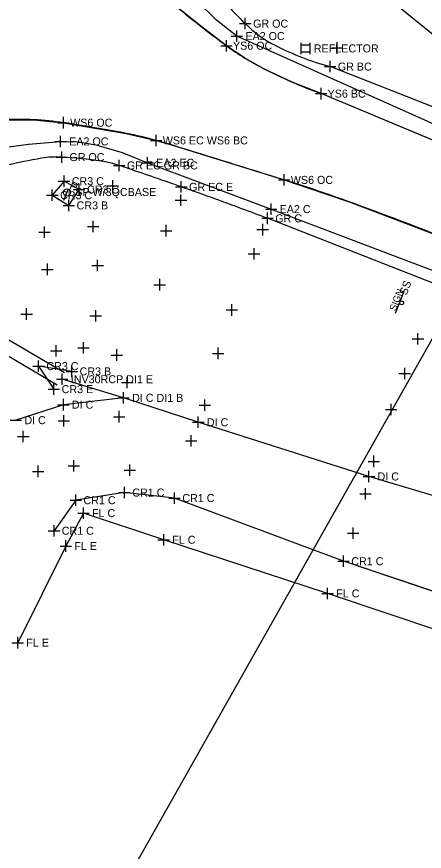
# Model space of a CAD drawing. Extents: x 1324236 to 1326110, y 459090 to 460782.
# Drawn here: x 1325026.2 to 1325097.4, y 459726.6 to 459872.5 of the extents above; entities that cross this region are included whole.
import ezdxf

# ---------------------------------------------------------------- set-up
doc = ezdxf.new("R2010")
doc.units = 0
for name, color, linetype in [('BD_X_Canopy', 7, 'Continuous'), ('DR_X_Ditch', 7, 'Continuous'), ('DR_X_Drive_Pipe', 7, 'Continuous'), ('DR_X_Paved_Gutter', 7, 'Continuous'), ('DT_X_Contour_Minor', 7, 'Continuous'), ('DT_X_Island', 7, 'Continuous'), ('DT_X_Terrain_Ground_Line', 7, 'Continuous'), ('DT_X_Void', 7, 'Continuous'), ('DV_X_Property_Line', 7, 'Continuous'), ('E-RW-ODOT', 7, 'Continuous'), ('PM_X_CL_Double_Solid', 7, 'Continuous'), ('PM_X_Edge_Line', 7, 'Continuous'), ('PM_X_Misc', 7, 'Continuous'), ('PM_X_Parking_Lot_Stall', 7, 'Continuous'), ('PV_X_Shoulder', 7, 'Continuous'), ('RD_X_Concrete_Barrier', 7, 'Continuous'), ('RW_X_CL', 7, 'Continuous'), ('RW_X_Esmt_SH', 7, 'Continuous'), ('SG_X_Foundation', 7, 'Continuous'), ('VG_X_Flower_Bed', 7, 'Continuous')]:
    doc.layers.add(name, color=color, linetype=linetype)

msp = doc.modelspace()

# ---------------------------------------------------------------- linework, layer by layer
at = {"layer": 'BD_X_Canopy'}
msp.add_lwpolyline([(1325035.81, 459810.51), (1325030, 459811.43), (1325032.66, 459807.4)], dxfattribs=at)
at = {"layer": 'DR_X_Ditch'}
for points in [[(1325232.73, 459798.38), (1325201.51, 459810.88), (1325169.12, 459823.7), (1325137.45, 459835.9), (1325108.1, 459847.12), (1325079.38, 459859.09), (1325074.32, 459861.12), (1325069.38, 459863.44), (1325069.38, 459863.44), (1325066.03, 459865.32), (1325062.84, 459867.47), (1325062.84, 459867.47), (1325058.04, 459871.12), (1325053.37, 459874.94)], [(1325023.99, 459854.53), (1325029.18, 459854.52), (1325034.35, 459854.01), (1325034.35, 459854.01), (1325045.33, 459852.14), (1325045.33, 459852.14), (1325050.53, 459850.91), (1325050.53, 459850.91), (1325053.41, 459850.06), (1325053.41, 459850.06), (1325072.92, 459844), (1325072.92, 459844), (1325084.48, 459840.09), (1325084.48, 459840.09), (1325102.8, 459833.11), (1325102.8, 459833.11), (1325131.65, 459821.96), (1325163.65, 459809.19), (1325195.86, 459796.31), (1325226.81, 459783.55)]]:
    msp.add_lwpolyline(points, dxfattribs=at)
at = {"layer": 'DR_X_Drive_Pipe'}
for p, q in [((1325044.84, 459805.88), (1325034.13, 459809.13)), ((1325044.84, 459805.88), (1325034.32, 459804.68)), ((1325057.91, 459801.61), (1325044.84, 459805.88)), ((1325034.32, 459804.68), (1325026.02, 459801.97)), ((1325087.75, 459792.13), (1325057.91, 459801.61)), ((1325119.04, 459782.76), (1325087.75, 459792.13))]:
    msp.add_line(p, q, dxfattribs=at)
at = {"layer": 'DR_X_Paved_Gutter'}
for p, q in [((1325034.44, 459843.77), (1325032.39, 459841.32)), ((1325037.1, 459842.32), (1325034.44, 459843.77)), ((1325035.28, 459839.54), (1325037.1, 459842.32)), ((1325032.39, 459841.32), (1325035.28, 459839.54))]:
    msp.add_line(p, q, dxfattribs=at)
at = {"layer": 'DT_X_Contour_Minor'}
msp.add_line((1325092.41, 459820.69), (1325093.88, 459824.55), dxfattribs=at)
msp.add_circle((1325093.46, 459822.5), 0.344, dxfattribs=at)
at = {"layer": 'DT_X_Island'}
for p, q in [((1325035.81, 459810.51), (1325030, 459811.43)), ((1325030, 459811.43), (1325032.66, 459807.4)), ((1325045.01, 459789.31), (1325036.49, 459787.96)), ((1325053.76, 459788.35), (1325045.01, 459789.31)), ((1325036.49, 459787.96), (1325032.69, 459782.63)), ((1325083.29, 459777.3), (1325053.76, 459788.35)), ((1325115.06, 459766.59), (1325083.29, 459777.3))]:
    msp.add_line(p, q, dxfattribs=at)
msp.add_lwpolyline([(1325361.32, 459658.63), (1325323.94, 459679.11), (1325296.43, 459693.93), (1325266.13, 459708.04), (1325257.3, 459711.78), (1325234.17, 459720.37), (1325205.31, 459734.58), (1325176, 459744.8), (1325161.88, 459749.12), (1325145.8, 459759.39), (1325115.06, 459766.59), (1325083.29, 459777.3), (1325053.76, 459788.35), (1325045.01, 459789.31), (1325036.49, 459787.96), (1325032.69, 459782.63)], dxfattribs=at)
at = {"layer": 'DT_X_Terrain_Ground_Line'}
for p, q in [((1325075.81, 459868), (1325075.81, 459866)), ((1325077.41, 459868), (1325077.41, 459866)), ((1325075.81, 459867.6), (1325077.41, 459867.6)), ((1325075.81, 459866.4), (1325077.41, 459866.4))]:
    msp.add_line(p, q, dxfattribs=at)
at = {"layer": 'DV_X_Property_Line'}
for p, q in [((1325064.65, 459868.16), (1325064.65, 459870.16)), ((1325063.65, 459869.16), (1325065.65, 459869.16)), ((1325032.85, 459850.73), (1325034.85, 459850.73)), ((1325033.85, 459849.73), (1325033.85, 459851.73)), ((1325049.06, 459845.99), (1325049.06, 459847.99)), ((1325048.06, 459846.99), (1325050.06, 459846.99)), ((1325069.63, 459838.89), (1325071.63, 459838.89)), ((1325070.63, 459837.89), (1325070.63, 459839.89)), ((1325034.13, 459808.13), (1325034.13, 459810.13)), ((1325033.13, 459809.13), (1325035.13, 459809.13))]:
    msp.add_line(p, q, dxfattribs=at)
at = {"layer": 'E-RW-ODOT'}
for p, q in [((1324967.69, 459977.08), (1325119.34, 459852.69)), ((1325119.34, 459852.69), (1324989.68, 459622.77))]:
    msp.add_line(p, q, dxfattribs=at)
at = {"layer": 'PM_X_CL_Double_Solid'}
for p, q in [((1325037.83, 459785.71), (1325034.74, 459779.96)), ((1325051.86, 459781.06), (1325037.83, 459785.71)), ((1325080.52, 459771.67), (1325051.86, 459781.06)), ((1325034.74, 459779.96), (1325026.34, 459763.05)), ((1325113.49, 459760.54), (1325080.52, 459771.67))]:
    msp.add_line(p, q, dxfattribs=at)
at = {"layer": 'PM_X_Edge_Line'}
msp.add_line((1325108.1, 459847.12), (1325079.38, 459859.09), dxfattribs=at)
for centre, radius, start, end in [((1325167.04, 460009.09), 175.82, 229.7248, 233.6569), ((1325090.35, 459904.86), 46.43, 233.6569, 243.1461), ((1325111.66, 459946.95), 93.6, 243.1461, 249.8253), ((1325026.54, 459801.82), 52.77, 81.4885, 92.769), ((1324993.67, 459582.23), 274.81, 79.1653, 81.4885), ((1325033.44, 459790), 63.26, 74.3221, 79.1653), ((1325018.93, 459738.3), 116.96, 72.853, 74.3221), ((1323453.63, 454665.03), 5426.22, 72.63736, 72.85303), ((1324994.59, 459593.48), 262.48, 69.9727, 72.6374), ((1324852.54, 459203.8), 677.25, 68.31393, 69.97272)]:
    msp.add_arc(centre, radius, start, end, dxfattribs=at)
at = {"layer": 'PM_X_Misc'}
msp.add_line((1325110.14, 459852.34), (1325080.96, 459863.83), dxfattribs=at)
for centre, radius, start, end in [((1325151.33, 459956.58), 120.53, 220.0757, 225.0151), ((1325080.85, 459886.06), 20.82, 225.0151, 243.1235), ((1325094.25, 459912.51), 50.47, 243.1235, 254.7245), ((1325064.42, 459660.73), 190.1, 100.2725, 104.1003), ((1325033.12, 459833.42), 14.59, 86.4268, 100.2725), ((1325028.75, 459763.46), 84.69, 81.7255, 86.4268), ((1325038.3, 459829.15), 18.31, 71.6041, 81.7255), ((1324992.5, 459691.45), 163.43, 70.9643, 71.6041), ((1323550.06, 455510.74), 4585.99, 70.84355, 70.96432), ((1324922.07, 459460.28), 404.92, 69.9406, 70.8435), ((1324742.66, 458968.94), 927.99, 69.34416, 69.9406)]:
    msp.add_arc(centre, radius, start, end, dxfattribs=at)
at = {"layer": 'PM_X_Parking_Lot_Stall'}
msp.add_line((1325099.55, 459825.72), (1325070.01, 459837.28), dxfattribs=at)
at = {"layer": 'PV_X_Shoulder'}
for points in [[(1325234.05, 459801.48), (1325202.93, 459814.43), (1325170.18, 459826.73), (1325138.85, 459838.46), (1325108.97, 459849.32), (1325064.65, 459869.16), (1325061.08, 459871.96), (1325057.84, 459875.14), (1325054.97, 459878.66), (1325052.52, 459882.48), (1325052.52, 459882.48), (1325050.29, 459887.07), (1325048.66, 459891.9), (1325047.65, 459896.9), (1325047.65, 459896.9), (1325048.1, 459908.06), (1325059.67, 459926.39), (1325068.28, 459937.87)], [(1325022.6, 459849.51), (1325028.21, 459850.26), (1325033.85, 459850.73), (1325033.85, 459850.73), (1325036.96, 459850.67), (1325040.02, 459850.16), (1325040.02, 459850.16), (1325044.62, 459848.79), (1325049.06, 459846.99), (1325049.06, 459846.99), (1325070.63, 459838.89), (1325100.31, 459827.64), (1325129.15, 459816.15), (1325160.37, 459803.77), (1325193.37, 459790.36), (1325224.54, 459777.85)]]:
    msp.add_lwpolyline(points, dxfattribs=at)
at = {"layer": 'RD_X_Concrete_Barrier'}
msp.add_line((1325034.43, 459840.48), (1325035.23, 459842.43), dxfattribs=at)
msp.add_circle((1325034.96, 459841.78), 0.63, dxfattribs=at)
at = {"layer": 'RW_X_CL'}
for p, q in [((1325062.84, 459866.47), (1325062.84, 459868.47)), ((1325082.17, 459866.08), (1325082.17, 459868.08)), ((1325061.84, 459867.47), (1325063.84, 459867.47)), ((1325081.17, 459867.08), (1325083.17, 459867.08)), ((1325079.38, 459858.09), (1325079.38, 459860.09)), ((1325078.38, 459859.09), (1325080.38, 459859.09)), ((1325034.35, 459853.01), (1325034.35, 459855.01)), ((1325033.35, 459854.01), (1325035.35, 459854.01)), ((1325050.53, 459849.91), (1325050.53, 459851.91)), ((1325049.53, 459850.91), (1325051.53, 459850.91)), ((1325034.44, 459842.77), (1325034.44, 459844.77)), ((1325072.92, 459843.01), (1325072.92, 459845.01)), ((1325033.44, 459843.77), (1325035.44, 459843.77)), ((1325037.1, 459841.32), (1325037.1, 459843.32)), ((1325042.99, 459841.97), (1325042.99, 459843.97)), ((1325071.92, 459844), (1325073.92, 459844)), ((1325032.39, 459840.32), (1325032.39, 459842.32)), ((1325036.1, 459842.32), (1325038.1, 459842.32)), ((1325041.99, 459842.97), (1325043.99, 459842.97)), ((1325031.39, 459841.32), (1325033.39, 459841.32)), ((1325035.28, 459838.54), (1325035.28, 459840.54)), ((1325053.88, 459840.45), (1325055.88, 459840.45)), ((1325054.88, 459839.45), (1325054.88, 459841.45)), ((1325034.28, 459839.54), (1325036.28, 459839.54)), ((1325031.03, 459833.85), (1325031.03, 459835.85)), ((1325038.52, 459835.83), (1325040.52, 459835.83)), ((1325039.52, 459834.83), (1325039.52, 459836.83)), ((1325052.29, 459834.12), (1325052.29, 459836.12)), ((1325069.17, 459834.3), (1325069.17, 459836.3)), ((1325030.03, 459834.85), (1325032.03, 459834.85)), ((1325051.29, 459835.12), (1325053.29, 459835.12)), ((1325068.17, 459835.3), (1325070.17, 459835.3)), ((1325067.65, 459830.07), (1325067.65, 459832.07)), ((1325040.32, 459828.04), (1325040.32, 459830.04)), ((1325066.65, 459831.07), (1325068.65, 459831.07)), ((1325031.53, 459827.35), (1325031.53, 459829.35)), ((1325039.32, 459829.04), (1325041.32, 459829.04)), ((1325030.53, 459828.35), (1325032.53, 459828.35)), ((1325050.16, 459825.67), (1325052.16, 459825.67)), ((1325051.16, 459824.67), (1325051.16, 459826.67)), ((1325027.91, 459819.54), (1325027.91, 459821.54)), ((1325039.98, 459819.24), (1325039.98, 459821.24)), ((1325062.79, 459821.25), (1325064.79, 459821.25)), ((1325063.79, 459820.25), (1325063.79, 459822.25)), ((1325026.91, 459820.54), (1325028.91, 459820.54)), ((1325038.98, 459820.24), (1325040.98, 459820.24)), ((1325096.31, 459815.19), (1325096.31, 459817.19)), ((1325037.83, 459813.62), (1325037.83, 459815.62)), ((1325095.31, 459816.19), (1325097.31, 459816.19)), ((1325032.06, 459814.09), (1325034.06, 459814.09)), ((1325033.06, 459813.09), (1325033.06, 459815.09)), ((1325036.83, 459814.62), (1325038.83, 459814.62)), ((1325043.66, 459812.37), (1325043.66, 459814.37)), ((1325061.38, 459812.66), (1325061.38, 459814.66)), ((1325042.66, 459813.37), (1325044.66, 459813.37)), ((1325060.38, 459813.66), (1325062.38, 459813.66)), ((1325029, 459811.43), (1325031, 459811.43)), ((1325030, 459810.43), (1325030, 459812.43)), ((1325035.81, 459809.51), (1325035.81, 459811.51)), ((1325093.99, 459809.14), (1325093.99, 459811.14)), ((1325034.81, 459810.51), (1325036.81, 459810.51)), ((1325045.5, 459807.57), (1325045.5, 459809.57)), ((1325092.99, 459810.14), (1325094.99, 459810.14)), ((1325032.66, 459806.4), (1325032.66, 459808.4)), ((1325044.5, 459808.57), (1325046.5, 459808.57)), ((1325031.66, 459807.4), (1325033.66, 459807.4)), ((1325059.07, 459803.58), (1325059.07, 459805.58)), ((1325058.07, 459804.58), (1325060.07, 459804.58)), ((1325090.61, 459803.85), (1325092.61, 459803.85)), ((1325091.61, 459802.85), (1325091.61, 459804.85)), ((1325034.39, 459800.86), (1325034.39, 459802.86)), ((1325043.08, 459802.58), (1325045.08, 459802.58)), ((1325044.08, 459801.58), (1325044.08, 459803.58)), ((1325033.39, 459801.86), (1325035.39, 459801.86)), ((1325027.32, 459798.1), (1325027.32, 459800.1)), ((1325056.65, 459797.36), (1325056.65, 459799.36)), ((1325026.32, 459799.1), (1325028.32, 459799.1)), ((1325055.65, 459798.36), (1325057.65, 459798.36)), ((1325036.16, 459792.97), (1325036.16, 459794.97)), ((1325088.58, 459793.77), (1325088.58, 459795.77)), ((1325029.91, 459792.02), (1325029.91, 459794.02)), ((1325035.16, 459793.97), (1325037.16, 459793.97)), ((1325045.96, 459792.24), (1325045.96, 459794.24)), ((1325087.58, 459794.77), (1325089.58, 459794.77)), ((1325028.91, 459793.02), (1325030.91, 459793.02)), ((1325044.96, 459793.24), (1325046.96, 459793.24)), ((1325044.01, 459789.31), (1325046.01, 459789.31)), ((1325045.01, 459788.31), (1325045.01, 459790.31)), ((1325053.76, 459787.35), (1325053.76, 459789.35)), ((1325087.12, 459788.09), (1325087.12, 459790.09)), ((1325035.49, 459787.96), (1325037.49, 459787.96)), ((1325036.49, 459786.97), (1325036.49, 459788.97)), ((1325052.76, 459788.35), (1325054.76, 459788.35)), ((1325086.12, 459789.09), (1325088.12, 459789.09)), ((1325032.69, 459781.63), (1325032.69, 459783.63)), ((1325031.69, 459782.63), (1325033.69, 459782.63)), ((1325083.99, 459782.19), (1325085.98, 459782.19)), ((1325084.99, 459781.19), (1325084.99, 459783.19)), ((1325083.29, 459776.3), (1325083.29, 459778.3)), ((1325082.29, 459777.3), (1325084.29, 459777.3))]:
    msp.add_line(p, q, dxfattribs=at)
at = {"layer": 'RW_X_Esmt_SH'}
for p, q in [((1325066.13, 459870.34), (1325066.13, 459872.34)), ((1325065.13, 459871.34), (1325067.13, 459871.34)), ((1325079.96, 459863.83), (1325081.96, 459863.83)), ((1325080.96, 459862.83), (1325080.96, 459864.83)), ((1325034.03, 459846.99), (1325034.03, 459848.99)), ((1325033.03, 459847.99), (1325035.03, 459847.99)), ((1325044.08, 459845.53), (1325044.08, 459847.53)), ((1325043.08, 459846.53), (1325045.08, 459846.53)), ((1325054.94, 459841.78), (1325054.94, 459843.78)), ((1325053.94, 459842.78), (1325055.94, 459842.78)), ((1325069.01, 459837.28), (1325071.01, 459837.28)), ((1325070.01, 459836.28), (1325070.01, 459838.28)), ((1325044.84, 459804.88), (1325044.84, 459806.88)), ((1325034.32, 459803.68), (1325034.32, 459805.68)), ((1325043.84, 459805.88), (1325045.84, 459805.88)), ((1325033.32, 459804.68), (1325035.32, 459804.68)), ((1325057.91, 459800.61), (1325057.91, 459802.61)), ((1325025.02, 459801.97), (1325027.02, 459801.97)), ((1325056.91, 459801.61), (1325058.91, 459801.61)), ((1325086.74, 459792.13), (1325088.75, 459792.13)), ((1325087.75, 459791.13), (1325087.75, 459793.13)), ((1325037.83, 459784.71), (1325037.83, 459786.71)), ((1325036.83, 459785.71), (1325038.83, 459785.71)), ((1325051.86, 459780.06), (1325051.86, 459782.06)), ((1325034.74, 459778.96), (1325034.74, 459780.96)), ((1325050.86, 459781.06), (1325052.86, 459781.06)), ((1325033.74, 459779.96), (1325035.74, 459779.96)), ((1325079.52, 459771.67), (1325081.52, 459771.67)), ((1325080.52, 459770.67), (1325080.52, 459772.67)), ((1325025.34, 459763.05), (1325027.34, 459763.05)), ((1325026.34, 459762.05), (1325026.34, 459764.05))]:
    msp.add_line(p, q, dxfattribs=at)
at = {"layer": 'SG_X_Foundation'}
msp.add_lwpolyline([(1325035.28, 459839.54), (1325037.1, 459842.32), (1325034.44, 459843.77), (1325032.39, 459841.32), (1325035.28, 459839.54)], dxfattribs=at)
at = {"layer": 'VG_X_Flower_Bed'}
for p, q in [((1324916.01, 459879.81), (1325034.53, 459810.31)), ((1324914.75, 459877.65), (1325033.27, 459808.16))]:
    msp.add_line(p, q, dxfattribs=at)

# ---------------------------------------------------------------- texts
at = {"layer": 'DT_X_Contour_Minor'}
for s, height, p in [('SS', 1.4, (1325094.31, 459823.72)), ('SIGN', 1.205, (1325092.4, 459820.98))]:
    msp.add_text(s, height=height, rotation=69.0999, dxfattribs=at).set_placement(p)
at = {"layer": 'DT_X_Void'}
msp.add_text('SP W/3QCBASE', height=1.4, dxfattribs=at).set_placement((1325036.41, 459841.18))
at = {"layer": 'DV_X_Property_Line'}
for s, p in [('EA2 OC', (1325066.15, 459868.46)), ('EA2 OC', (1325035.35, 459850.03)), ('EA2 EC', (1325050.56, 459846.29)), ('EA2 C', (1325072.13, 459838.19)), ('INV30RCP DI1 E', (1325035.63, 459808.43))]:
    msp.add_text(s, height=1.4, dxfattribs=at).set_placement(p)
at = {"layer": 'RD_X_Concrete_Barrier'}
msp.add_text('P', height=1.5, rotation=337.5827, dxfattribs=at).set_placement((1325035.23, 459842.43))
at = {"layer": 'RW_X_CL'}
for s, p in [('YS6 OC', (1325063.97, 459866.77)), ('YS6 BC', (1325080.51, 459858.39)), ('WS6 OC', (1325035.51, 459853.31)), ('WS6 EC WS6 BC', (1325051.7, 459850.21)), ('WS6 OC', (1325074.08, 459843.3)), ('CR3 C', (1325035.8, 459843.07)), ('CR3 C', (1325033.75, 459840.62)), ('CR3 C', (1325038.46, 459841.62)), ('CR3 B', (1325036.64, 459838.84)), ('CR3 C', (1325031.36, 459810.73)), ('CR3 B', (1325037.16, 459809.81)), ('CR3 E', (1325034.02, 459806.7)), ('CR1 C', (1325046.37, 459788.61)), ('CR1 C', (1325037.84, 459787.27)), ('CR1 C', (1325055.12, 459787.65)), ('CR1 C', (1325034.04, 459781.93)), ('CR1 C', (1325084.65, 459776.6))]:
    msp.add_text(s, height=1.4, dxfattribs=at).set_placement(p)
at = {"layer": 'RW_X_Esmt_SH'}
for s, p in [('GR OC', (1325067.49, 459870.64)), ('REFLECTOR', (1325078.11, 459866.3)), ('GR BC', (1325082.31, 459863.12)), ('GR OC', (1325035.38, 459847.29)), ('GR EC GR BC', (1325045.44, 459845.83)), ('GR EC E', (1325056.3, 459842.08)), ('GR C', (1325071.37, 459836.58)), ('DI C', (1325035.82, 459803.98)), ('DI C DI1 B', (1325046.34, 459805.18)), ('DI C', (1325027.52, 459801.27)), ('DI C', (1325059.41, 459800.91)), ('DI C', (1325089.25, 459791.43)), ('FL C', (1325039.33, 459785.01)), ('FL E', (1325036.24, 459779.26)), ('FL C', (1325053.36, 459780.36)), ('FL C', (1325082.02, 459770.97)), ('FL E', (1325027.84, 459762.35))]:
    msp.add_text(s, height=1.4, dxfattribs=at).set_placement(p)

doc.saveas('drawing.dxf')
